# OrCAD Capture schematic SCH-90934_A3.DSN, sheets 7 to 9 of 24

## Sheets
7 C-20 REMOTE DEBUG: size A1
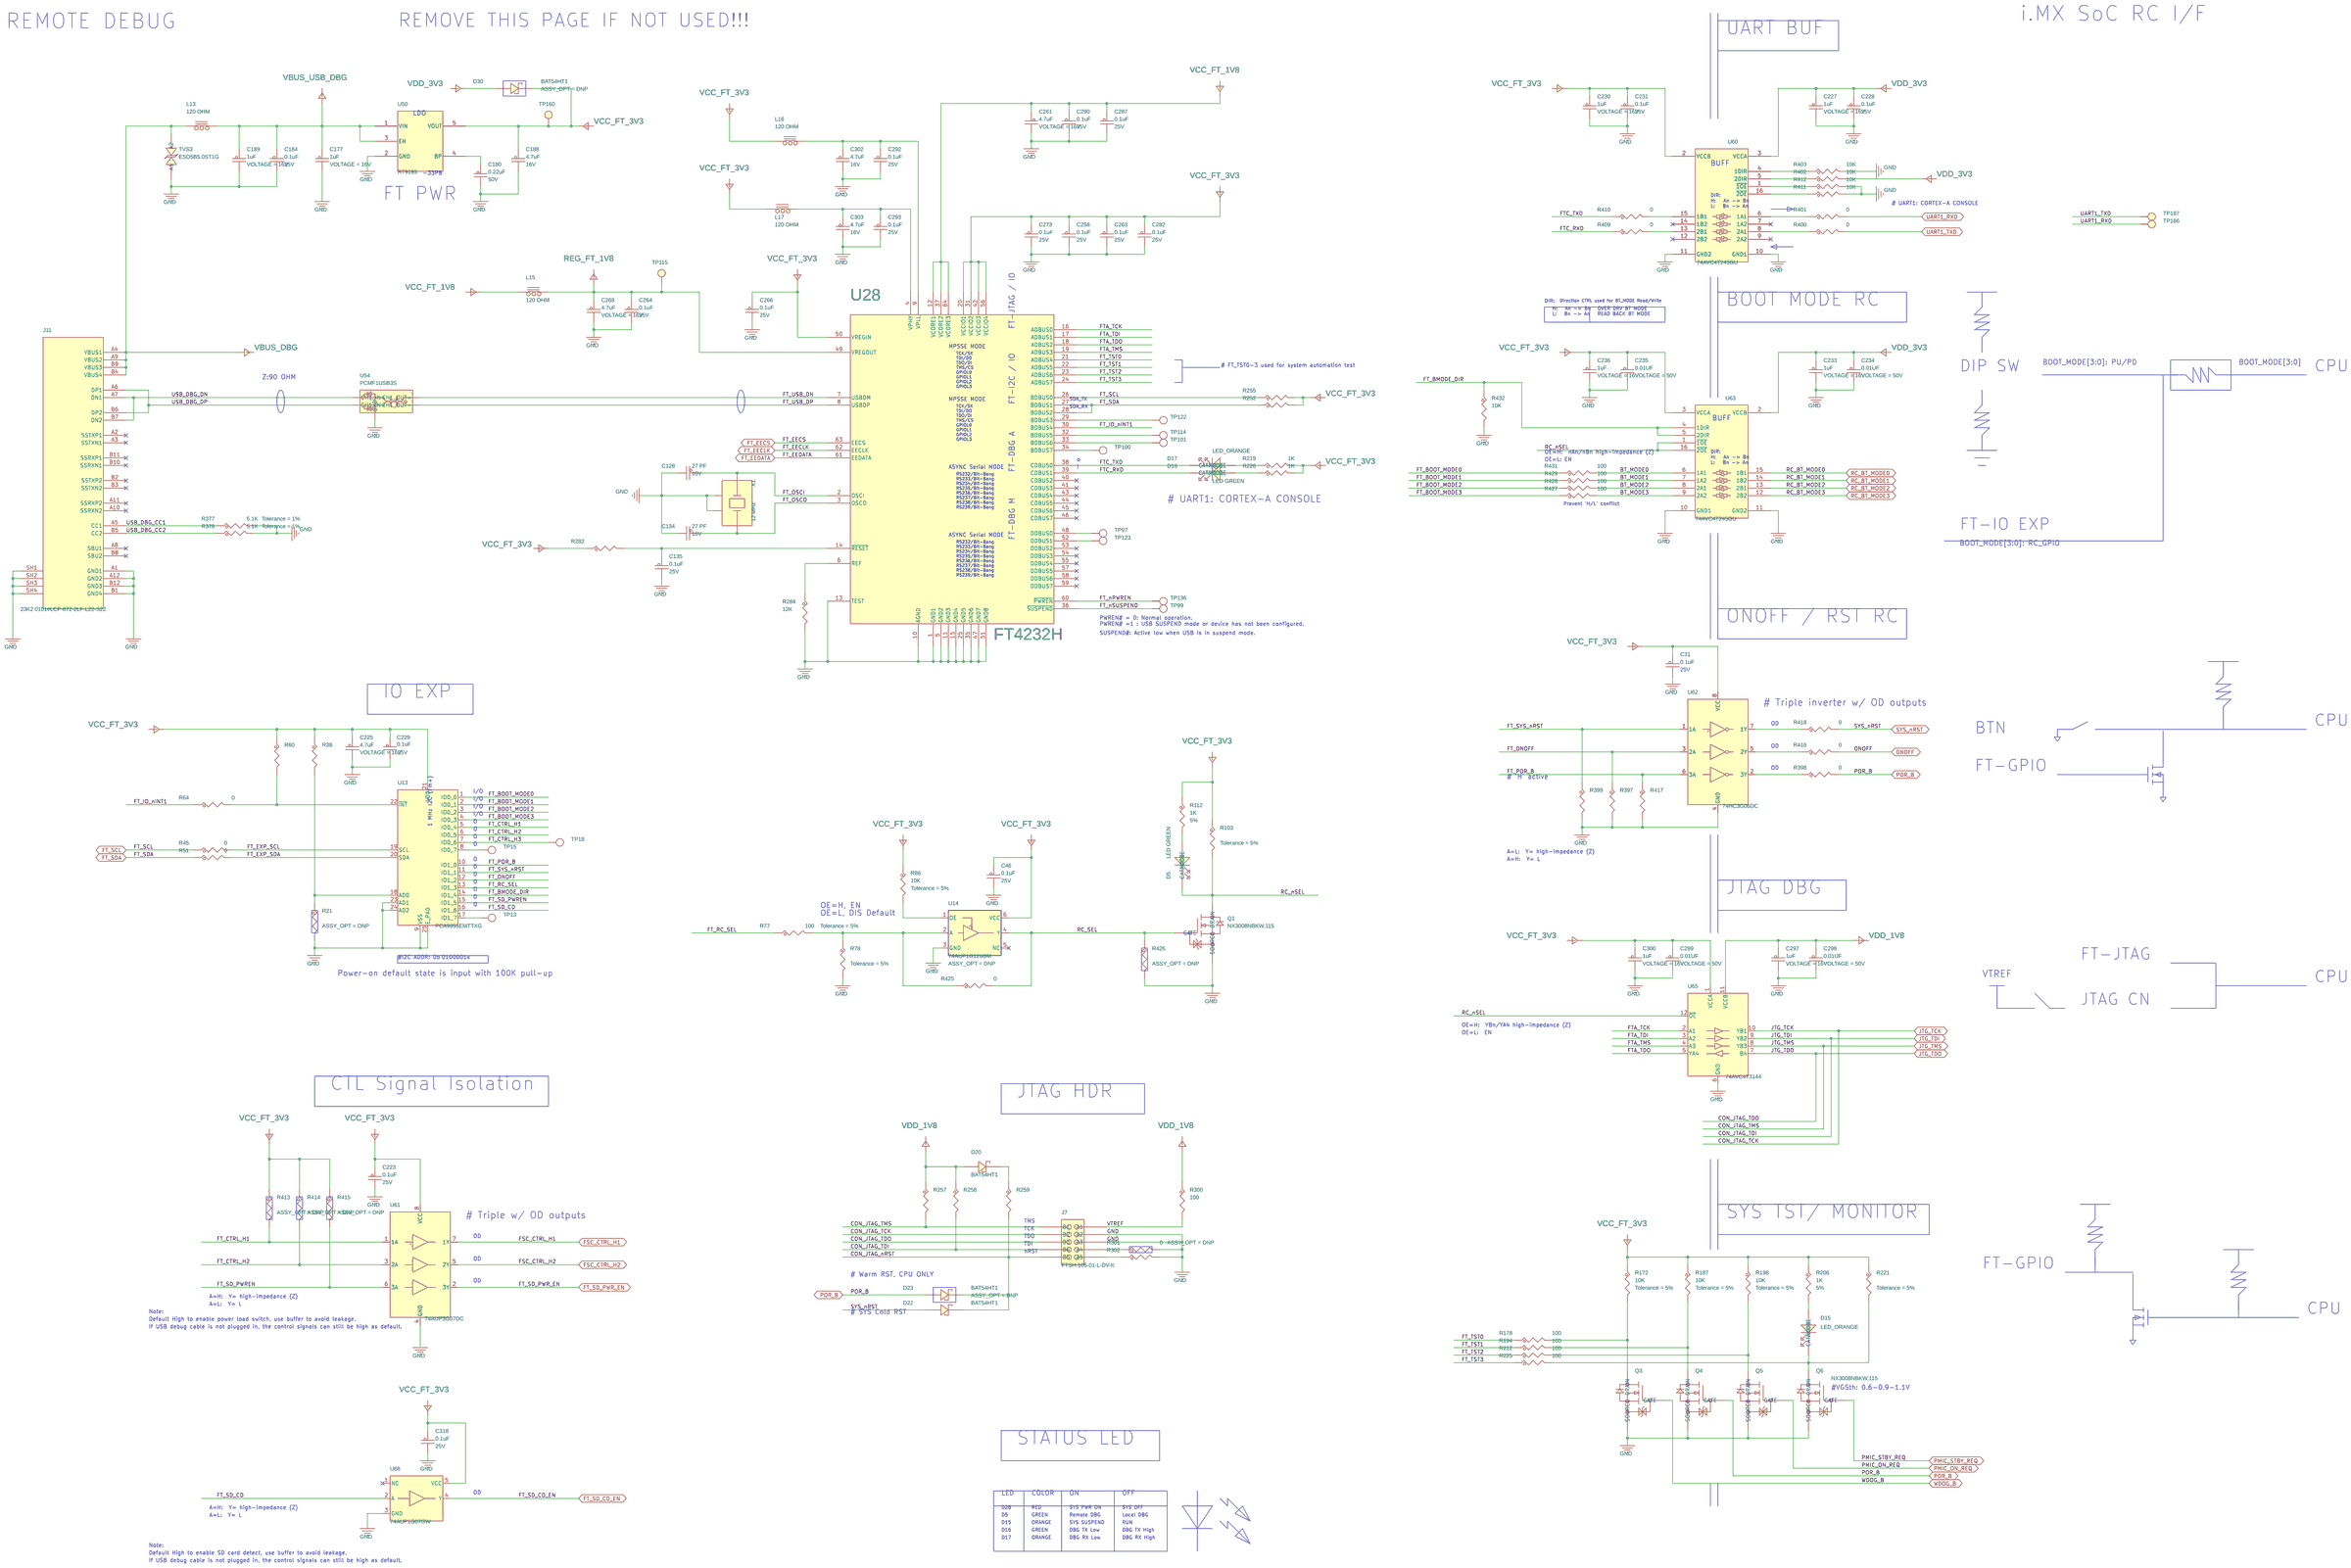
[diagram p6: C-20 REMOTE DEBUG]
8 C-19 PDM MIC: size A3
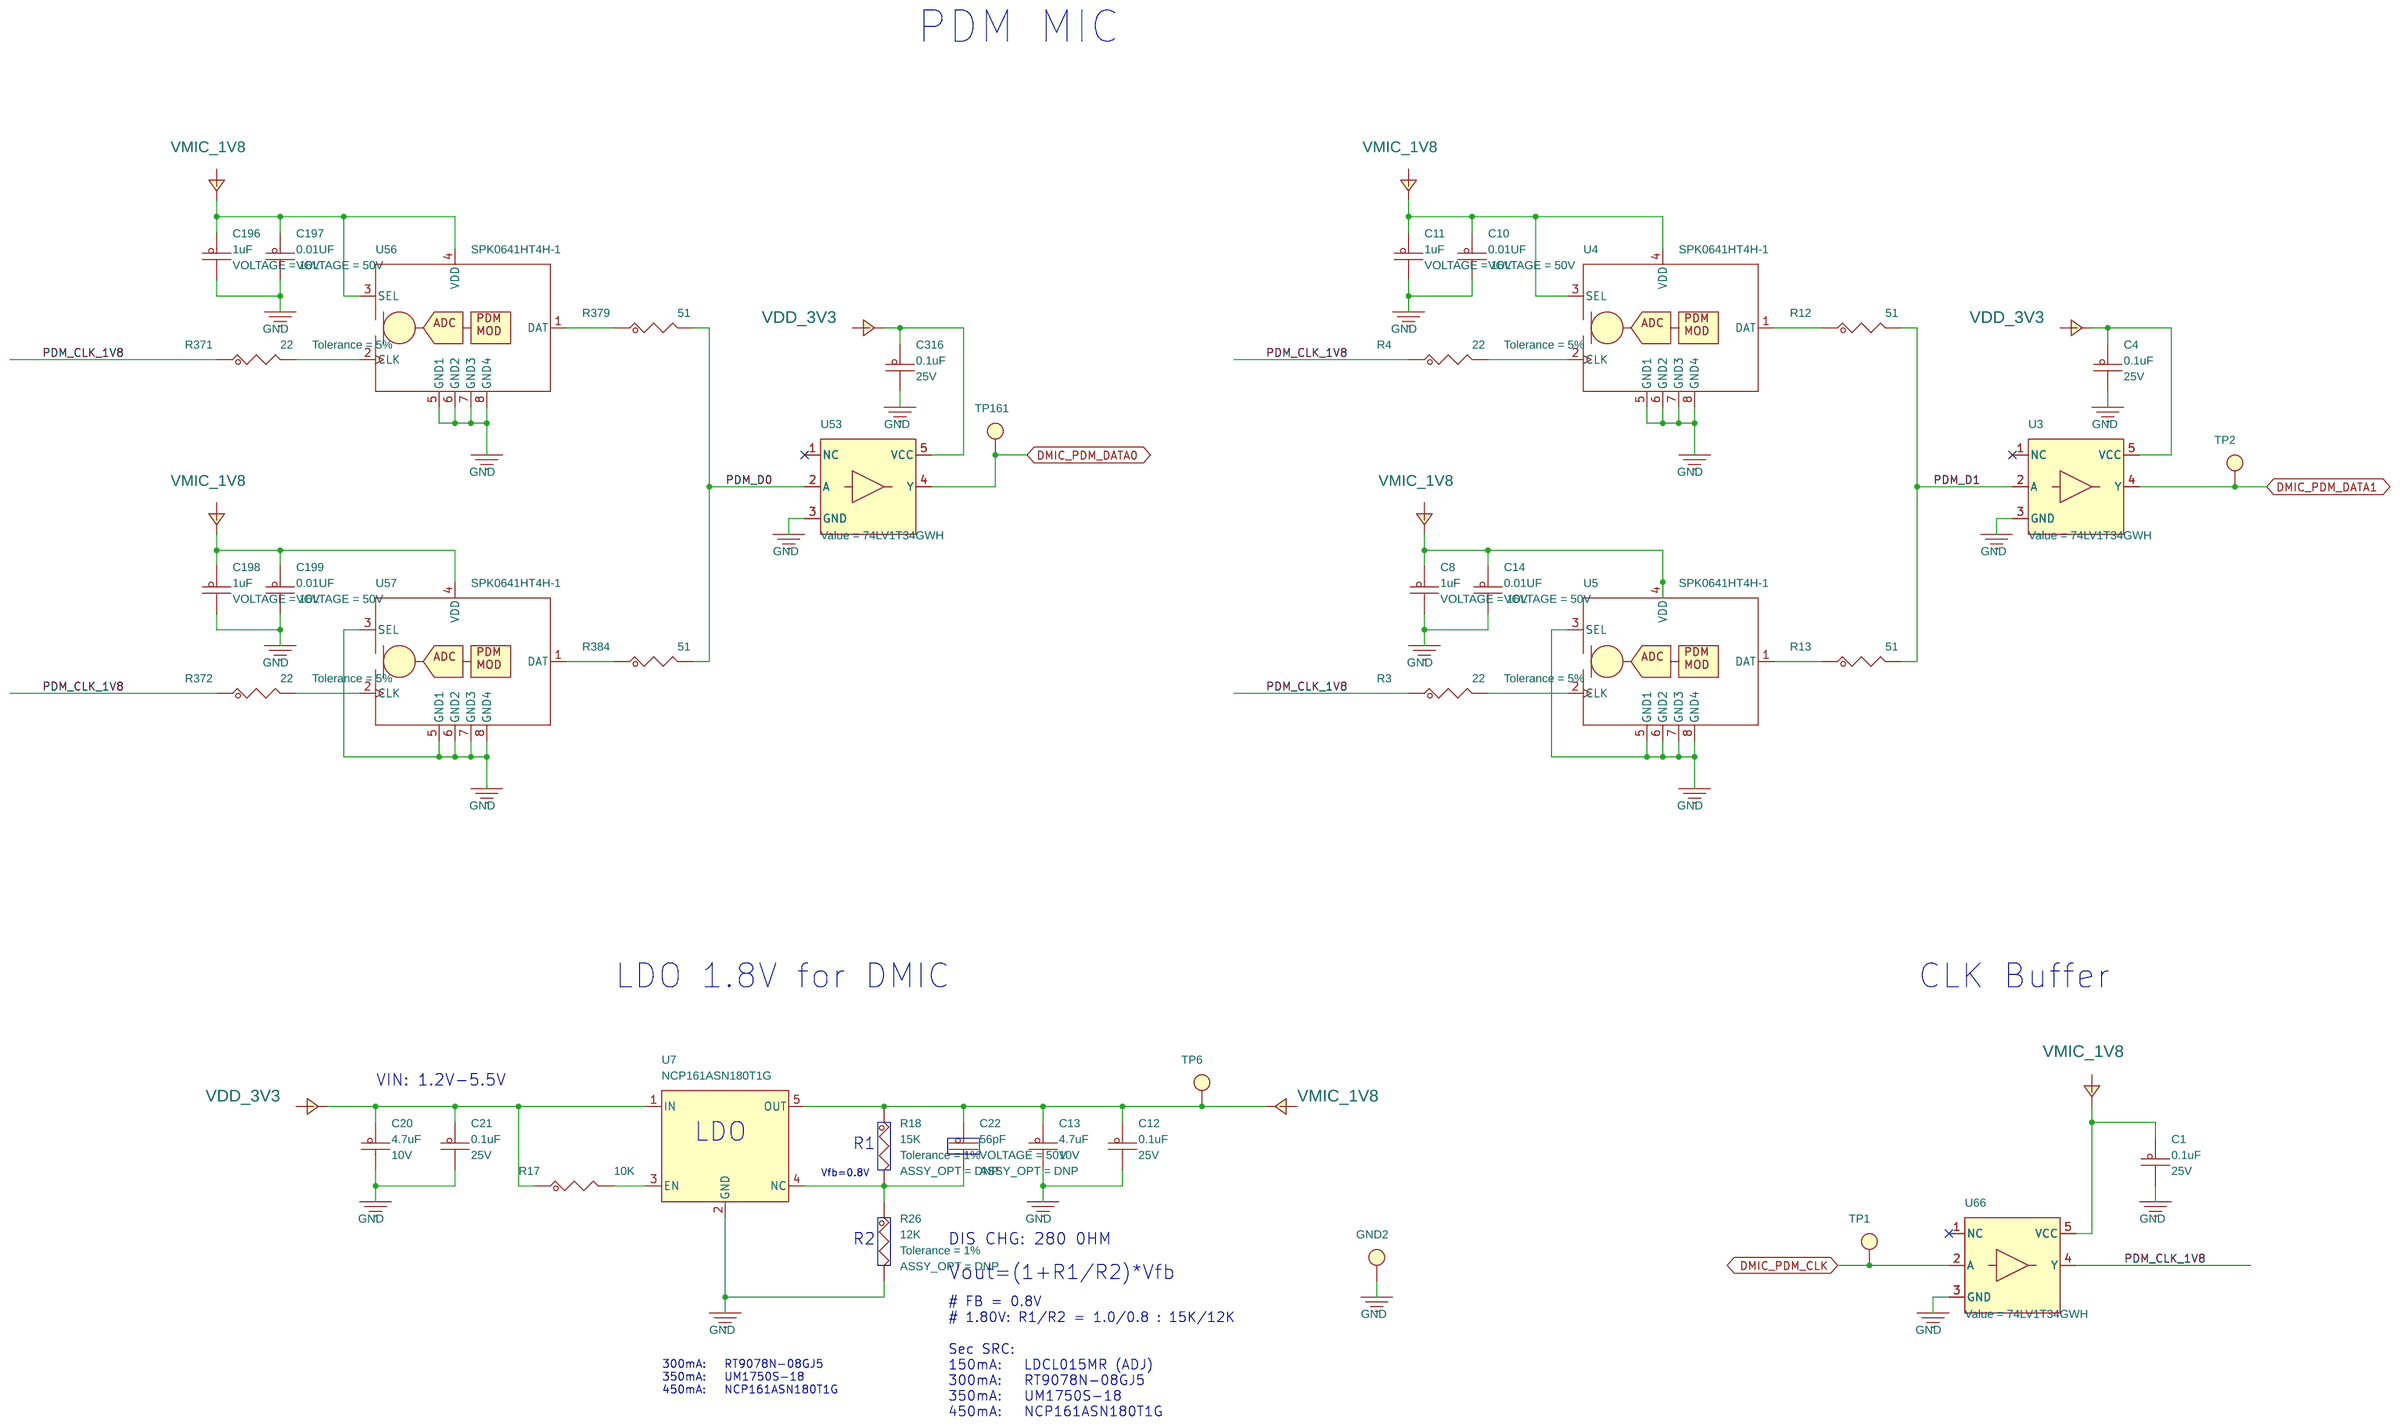
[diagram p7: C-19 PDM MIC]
9 C-18 AUDIO DAC: size A4
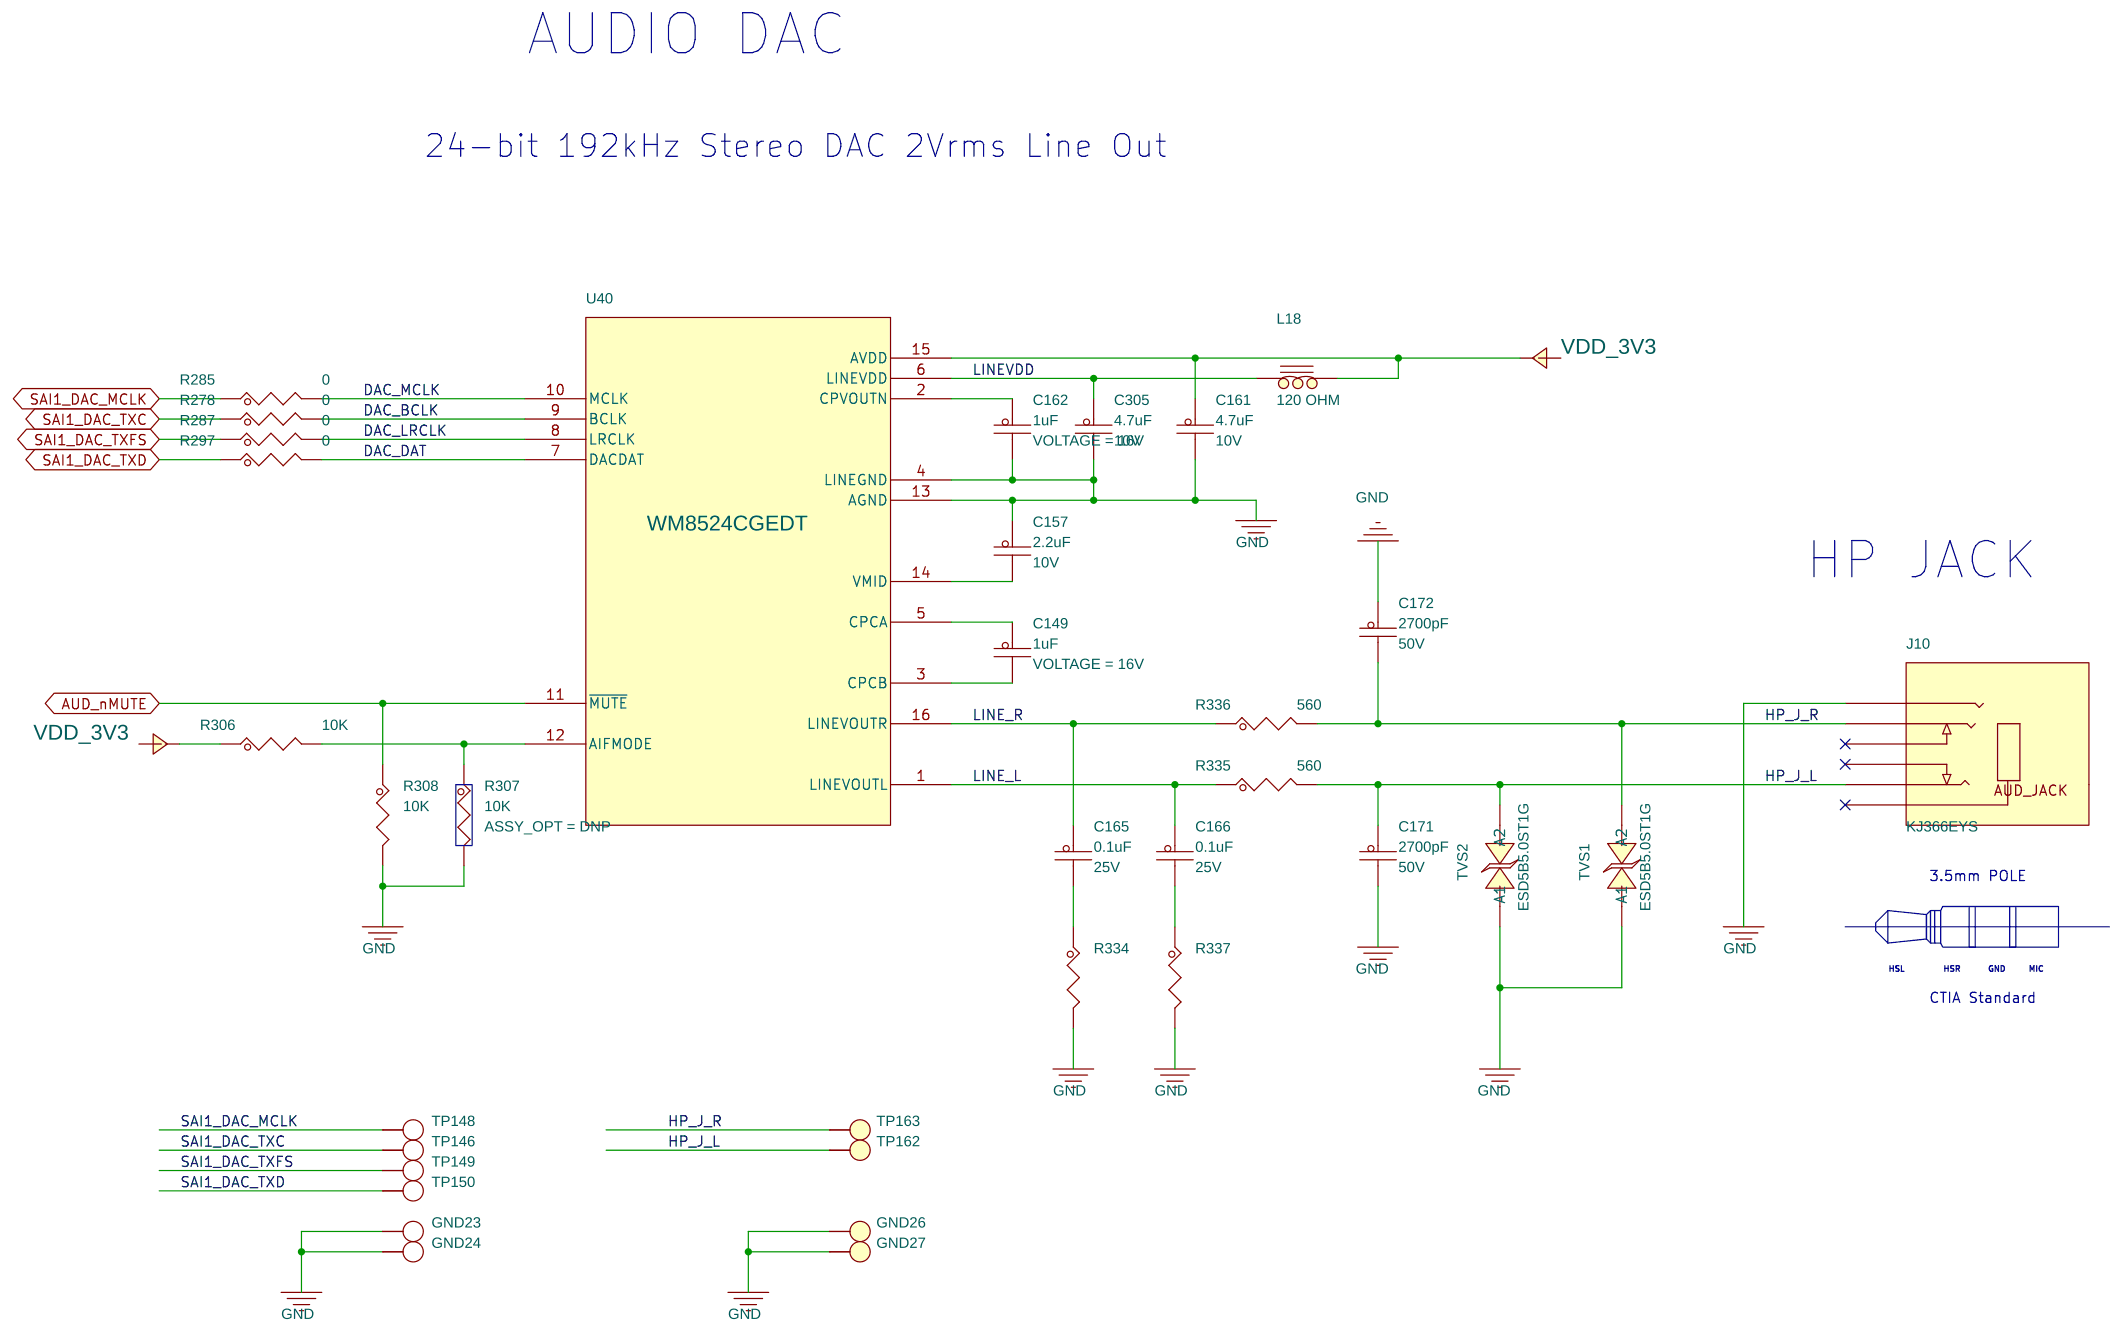
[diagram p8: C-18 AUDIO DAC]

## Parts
sheet C-18 AUDIO DAC
C149  1uF  [CC0402_25]
C157  2.2uF  [CC0402_25]
C161  4.7uF  [cc0402_tol0p15]
C162  1uF  [CC0402_25]
C165  0.1uF  [CC0402_25]
C166  0.1uF  [CC0402_25]
C171  2700pF  [0603_CC]
C172  2700pF  [0603_CC]
C305  4.7uF  [cc0402_tol0p15]
GND23  TPAD_020  [tpad_020]
GND24  TPAD_020  [tpad_020]
GND26  TP_35MIL  [testpoint_35mil]
GND27  TP_35MIL  [testpoint_35mil]
J10  KJ366EYS  [con6_audiojack_ra_th]
L18  120 OHM  [IND_0603]
R278  0  [0402_CC]
R285  0  [0402_CC]
R287  0  [0402_CC]
R297  0  [0402_CC]
R306  10K  [0402_CC]
R307  10K  [0402_CC]
R308  10K  [0402_CC]
R334  20  [0603_CC]
R335  560  [0603_CC]
R336  560  [0603_CC]
R337  20  [0603_CC]
TP146  TPAD_020  [tpad_020]
TP148  TPAD_020  [tpad_020]
TP149  TPAD_020  [tpad_020]
TP150  TPAD_020  [tpad_020]
TP162  TP_35MIL  [testpoint_35mil]
TP163  TP_35MIL  [testpoint_35mil]
TVS1  ESD5B5.0ST1G  [diode2_sod523]
TVS2  ESD5B5.0ST1G  [diode2_sod523]
U40  WM8524CGEDT  [tssop16]
sheet C-19 PDM MIC
C1  0.1uF  [CC0402_25]
C4  0.1uF  [CC0402_25]
C8  1uF  [CC0402_25]
C10  0.01UF  [CC0402_25]
C11  1uF  [CC0402_25]
C12  0.1uF  [CC0402_25]
C13  4.7uF  [cc0402_tol0p15]
C14  0.01UF  [CC0402_25]
C20  4.7uF  [cc0402_tol0p15]
C21  0.1uF  [CC0402_25]
C22  56pF  [CC0402_25]
C196  1uF  [CC0402_25]
C197  0.01UF  [CC0402_25]
C198  1uF  [CC0402_25]
C199  0.01UF  [CC0402_25]
C316  0.1uF  [CC0402_25]
GND2  TP_35MIL  [testpoint_35mil]
R3  22  [0402_CC]
R4  22  [0402_CC]
R12  51  [0402_CC]
R13  51  [0402_CC]
R17  10K  [0402_CC]
R18  15K  [RC0402_25]
R26  12K  [RC0402_25]
R371  22  [0402_CC]
R372  22  [0402_CC]
R379  51  [0402_CC]
R384  51  [0402_CC]
TP1  TP_35MIL  [testpoint_35mil]
TP2  TP_35MIL  [testpoint_35mil]
TP6  TP_35MIL  [testpoint_35mil]
TP161  TP_35MIL  [testpoint_35mil]
U3  74LV1T34GWH  [sc70-5]
U4  SPK0641HT4H-1  [lga8_3p1x4p1mm_spk0641]
U5  SPK0641HT4H-1  [lga8_3p1x4p1mm_spk0641]
U7  NCP161ASN180T1G  [SOT-23-5]
U53  74LV1T34GWH  [sc70-5]
U56  SPK0641HT4H-1  [lga8_3p1x4p1mm_spk0641]
U57  SPK0641HT4H-1  [lga8_3p1x4p1mm_spk0641]
U66  74LV1T34GWH  [sc70-5]
sheet C-20 REMOTE DEBUG
C31  0.1uF  [CC0402_25]
C46  0.1uF  [CC0402_25]
C128  27 PF  [CC0402_25]
C134  27 PF  [CC0402_25]
C135  0.1uF  [CC0402_25]
C177  1uF  [CC0402_25]
C180  0.22uF  [CC0402_25]
C184  0.1uF  [CC0402_25]
C188  4.7uF  [cc0402_tol0p15]
C189  1uF  [CC0402_25]
C223  0.1uF  [CC0402_25]
C225  4.7uF  [cc0402_tol0p15]
C227  1uF  [CC0402_25]
C228  0.1uF  [CC0402_25]
C229  0.1uF  [CC0402_25]
C230  1uF  [CC0402_25]
C231  0.1uF  [CC0402_25]
C233  1uF  [CC0402_25]
C234  0.01UF  [CC0402_25]
C235  0.01UF  [CC0402_25]
C236  1uF  [CC0402_25]
C258  0.1uF  [CC0402_25]
C261  4.7uF  [cc0402_tol0p15]
C263  0.1uF  [CC0402_25]
C264  0.1uF  [CC0402_25]
C266  0.1uF  [CC0402_25]
C268  4.7uF  [cc0402_tol0p15]
C273  0.1uF  [CC0402_25]
C282  0.1uF  [CC0402_25]
C287  0.1uF  [CC0402_25]
C290  0.1uF  [CC0402_25]
C292  0.1uF  [CC0402_25]
C293  0.1uF  [CC0402_25]
C297  1uF  [CC0402_25]
C298  0.01UF  [CC0402_25]
C299  0.01UF  [CC0402_25]
C300  1uF  [CC0402_25]
C302  4.7uF  [cc0402_tol0p15]
C303  4.7uF  [cc0402_tol0p15]
C318  0.1uF  [CC0402_25]
D5  LED GREEN  [LED_0603]
D15  LED_ORANGE  [led_0603_11mil]
D16  LED GREEN  [LED_0603]
D17  LED_ORANGE  [led_0603_11mil]
D20  BAT54HT1  [SOD323]
D22  BAT54HT1  [SOD323]
D23  BAT54HT1  [SOD323]
D30  BAT54HT1  [SOD323]
J7  FTSH-105-01-L-DV-K  [hdr205_10m_50_sm_k]
J11  23K2 0101#LCP-872-2LF-L22-S22  [con24_usb_typec_ra_smt_th_2p2l]
L13  120 OHM  [IND_0603]
L15  120 OHM  [IND_0603]
L16  120 OHM  [IND_0603]
L17  120 OHM  [IND_0603]
Q1  NX3008NBKW,115  [sc70_3]
Q3  NX3008NBKW,115  [sc70_3]
Q4  NX3008NBKW,115  [sc70_3]
Q5  NX3008NBKW,115  [sc70_3]
Q6  NX3008NBKW,115  [sc70_3]
R21  10K  [0402_CC]
R38  10K  [0402_CC]
R45  0  [0402_CC]
R51  0  [0402_CC]
R60  10K  [0402_CC]
R64  0  [0402_CC]
R77  100  [RC0402_25]
R78  10K  [0402_CC]
R86  10K  [0402_CC]
R103  10K  [0402_CC]
R112  1K  [0402_CC]
R172  10K  [0402_CC]
R178  100  [RC0402_25]
R187  10K  [0402_CC]
R194  100  [RC0402_25]
R198  10K  [0402_CC]
R206  1K  [0402_CC]
R212  100  [RC0402_25]
R219  1K  [0402_CC]
R221  10K  [0402_CC]
R225  100  [RC0402_25]
R226  1K  [0402_CC]
R252  2.2K  [0402_CC]
R255  2.2K  [0402_CC]
R257  10K  [0402_CC]
R258  10K  [0402_CC]
R259  10K  [0402_CC]
R282  10K  [0402_CC]
R284  12K  [0402_CC]
R300  100  [RC0402_25]
R301  0  [0402_CC]
R302  0  [0402_CC]
R377  5.1K  [RC0402_25]
R378  5.1K  [RC0402_25]
R397  10K  [0402_CC]
R398  0  [0402_CC]
R399  10K  [0402_CC]
R400  0  [0402_CC]
R401  0  [0402_CC]
R402  10K  [0402_CC]
R403  10K  [0402_CC]
R409  0  [0402_CC]
R410  0  [0402_CC]
R411  10K  [0402_CC]
R412  10K  [0402_CC]
R413  10K  [0402_CC]
R414  10K  [0402_CC]
R415  10K  [0402_CC]
R416  0  [0402_CC]
R417  10K  [0402_CC]
R418  0  [0402_CC]
R425  0  [0402_CC]
R426  10K  [0402_CC]
R427  100  [RC0402_25]
R428  100  [RC0402_25]
R429  100  [RC0402_25]
R431  100  [RC0402_25]
R432  10K  [0402_CC]
TP13  TPAD_020  [tpad_020]
TP15  TPAD_020  [tpad_020]
TP18  TPAD_020  [tpad_020]
TP97  TPAD_020  [tpad_020]
TP99  TPAD_020  [tpad_020]
TP100  TPAD_020  [tpad_020]
TP101  TPAD_020  [tpad_020]
TP114  TPAD_020  [tpad_020]
TP115  TP_35MIL  [testpoint_35mil]
TP122  TPAD_020  [tpad_020]
TP123  TPAD_020  [tpad_020]
TP136  TPAD_020  [tpad_020]
TP160  TP_35MIL  [testpoint_35mil]
TP186  TP_35MIL  [testpoint_35mil]
TP187  TP_35MIL  [testpoint_35mil]
TVS3  ESD5B5.0ST1G  [diode2_sod523]
U13  PCA9655EMTTXG  [qfn24_4X4_ep2p25mm]
U14  74AUP1G126GM  [udfn6_1x1p5mm]
U28  FT4232H  [lqfp64_0p5_10x10]
U50  RT9193  [sot23-5]
U54  PCMF1USB3S  [wlcsp5_0p4_0p82x1p22]
U60  74AVC4T245GU  [xqfn16_0p4_2p7x1p9]
U61  74AUP3G07DC  [ssop8_dcu]
U62  74HC3G06DC  [ssop8_dcu]
U63  74AVC4T245GU  [xqfn16_0p4_2p7x1p9]
U65  74AVC4T3144  [xqfn12_0p4_1p8x2p1]
U68  74AUP1G07GW  [sc70-5]
X1  12 MHz  [xtal_4_3p3x2p6mm]

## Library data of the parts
C149 C162 C189 = CAP_NP: CAP CER 1uF 16V 10% X5R 0402; AGILE_PN: 150-78973; CAD_APPROVED: Yes; FPLIST: CC0402_25,CC0402_HD,0402_CC,capc0402_l; HEIGHT: 0.55 MM; MFG_NAME01: TDK; MFG_PN01: C1005X5R1C105K; ROHS: Yes; Rated Voltage: 16V; Temp Range: -55C to +85C; Tolerance: 10%; VOLTAGE: 16V; voltage rating: 16V
C157 = CAP_NP: CAP CER 2.2uF 10V 10% X5R 0402; AGILE_PN: 150-78974; CAD_APPROVED: Yes; FPLIST: CC0402_25,CC0402_HD,0402_CC,capc0402_l; HEIGHT: 0.55 MM; MFG_NAME01: TDK; MFG_PN01: C1005X5R1A225K; Package Size: 0402; ROHS: Yes; Rated Voltage: 10V; Temp Range: -55C to +85C; Tolerance: 10%; VOLTAGE: 10V
C13 C20 C161 C305 = CAP_NP: CAP CER 4.7uF 10V 10% X5R 0402; AGILE_PN: 150-80044; CAD_APPROVED: Yes; FPLIST: cc0402_tol0p15,cc0402_tol0p15_ov,0402_cc_nsp; HEIGHT: 0.65MM; MFG_NAME01: SAMSUNG ELECTRO MECHANICS; MFG_PN01: CL05A475KP5NRNC; ROHS: Yes; Rated Voltage: 10V; Temp Range: -55C to +85C; Tolerance: 10%; VOLTAGE: 10V
C1 C4 C12 C21 C31 C46 C135 C165 C166 C184 C223 C228 C229 C231 C258 C263 C264 C266 C273 C282 C287 C290 C292 C293 C316 C318 = CAP_NP: CAP CER 0.1UF 25V 10% X5R 0402; AGILE_PN: 150-78633; CAD_APPROVED: Yes; FPLIST: CC0402_25,CC0402_HD,0402_CC,capc0402_l; HEIGHT: 0.55MM; MFG_NAME01: YAGEO AMERICA; MFG_PN01: CC0402KRX5R8BB104; Package Size: 0402; ROHS: Yes; Rated Voltage: 25V; Temp Range: -55C to +85C; Tolerance: 10%; VOLTAGE: 25V
C171 C172 = CAP_NP: CAP CER 2700pF 50V 5% C0G 0603; AGILE_PN: 150-78873; CAD_APPROVED: Yes; FPLIST: CC0603_OV,CC0603,0603_CC; HEIGHT: 0.87MM; MFG_NAME01: KEMET; MFG_PN01: C0603C272J5GACTU; Package Size: 0603; Package Type: Tape & reel; ROHS: Yes; Rated Voltage: 50V; Temp Range: -55C to +125C; Tolerance: 5%; VOLTAGE: 50V
GND23 GND24 TP13 TP15 TP18 TP97 TP99-TP101 TP114 TP122 TP123 TP136 TP146 TP148-TP150 = TESTLOOP: TEST POINT PAD 0.5MM DIA SMT, NO PART TO ORDER; AGILE_PN: 211-77484; ASSY_OPT: DNP; CAD_APPROVED: Yes; HEIGHT: 0.1MM; ROHS: Yes
GND2 GND26 GND27 TP1 TP2 TP6 TP115 TP160-TP163 TP186 TP187 = T_POINT_R: TEST POINT PAD .035 SMT, no part to order; AGILE_PN: 510-75618; ASSY_OPT: DNP; CAD_APPROVED: Yes; HEIGHT: 0.1MM; ROHS: Yes
J10 = CON_KJ366EYS_AUDIOJACK_6P: CON 6 AUDIO JACK 3.5MM SKT RA SMT -- 177H AU; AGILE_PN: 211-80200; CAD_APPROVED: Yes; HEIGHT: 4.5; MFG_NAME01: FODOT ELECTRONICS CO.,LTD.; MFG_PN01: KJ366EYS-00RJ03B; ROHS: Yes; Temp Range: -25 to +85°C; Temp_Range: -25 to +85°C
L13 L15-L18 = BEAD_0: IND FER BEAD 120OHM@100MHZ 2A 25% 0603; AGILE_PN: 180-78419; CAD_APPROVED: Yes; FPLIST: IND_0603,0603_CC; HEIGHT: 0.95; MFG_NAME01: MURATA; MFG_PN01: BLM18PG121SN1D; ROHS: Yes
R64 R278 R285 R287 R297 R398 R400 R401 R409 R410 R416 R418 R425 = RES: RES MF ZERO OHM 1/16W 5% 0402; AGILE_PN: 470-75394; CAD_APPROVED: Yes; FPLIST: RC0402_25,RC0402_HD,RC0402_X2,0402_CC; HEIGHT: 0.45; MFG_NAME01: YAGEO AMERICA; MFG_PN01: RC0402JR-070RL; ROHS: Yes; Temp Range: -55 to +155C; Tolerance: 5%; VOLTAGE: 1/16W
R17 R38 R60 R78 R86 R103 R172 R187 R198 R221 R257-R259 R282 R306 R308 R397 R399 R402 R403 R411 R412 R417 R432 = RES: RES MF 10K 1/16W 5% 0402; AGILE_PN: 470-75557; CAD_APPROVED: Yes; FPLIST: RC0402_25,RC0402_HD,0402_CC; HEIGHT: 0.4 MM; MFG_NAME01: VISHAY INTERTECHNOLOGY; MFG_PN01: CRCW040210K0JNED; ROHS: Yes; Tolerance: 5%
R21 R307 R413-R415 R426 = RES: RES MF 10K 1/16W 5% 0402; AGILE_PN: 470-75557; ASSY_OPT: DNP; CAD_APPROVED: Yes; FPLIST: RC0402_25,RC0402_HD,0402_CC; HEIGHT: 0.4 MM; MFG_NAME01: VISHAY INTERTECHNOLOGY; MFG_PN01: CRCW040210K0JNED; ROHS: Yes; Tolerance: 5%
R334 R337 = RES: RES MF 20.0OHM 1/10W 1% 0603; AGILE_PN: 470-75405; CAD_APPROVED: Yes; FPLIST: RC0603_OV,RC0603,0603_CC; HEIGHT: 0.55 MM; MFG_NAME01: KOA SPEER; MFG_PN01: RK73H1JTTD20R0F; ROHS: Yes; SIGNAL_MODEL: DEFAULT_RESISTOR_20OHM_2_1; Tolerance: 1%
R335 R336 = RES: RES TF 560 OHM 1/10W 5% 200PPM/C 0603; AGILE_PN: 470-81150; CAD_APPROVED: Yes; FPLIST: RC0603_OV,RC0603,0603_CC; HEIGHT: 0.55MM; MFG_NAME01: BOURNS; MFG_PN01: CR0603-JW-561ELF; ROHS: Yes; Tolerance: 5%
TVS1-TVS3 = DIODE_TVS_BIDIR: DIODE SUPPRESSOR 16A@30NS 5V@1UA SOD-523; 3D_Mechanical_Footprint_File: http://fcl.am.freescale.net/ALLEGRO/step/diode2_sod523.STEP; AGILE_PN: 480-76937; CAD_APPROVED: Yes; HEIGHT: 0.7; MFG_NAME01: ON SEMICONDUCTOR; ROHS: Yes
U40 = WM8524GEDT: IC DAC STEREO 24BIT 192kHz 2.97-3.63V TSSOP16; 3D_Mechanical_Footprint_File: http://fcl.am.freescale.net/ALLEGRO/step/tssop16.step; AGILE_PN: 315-81421; CAD_APPROVED: Yes; HEIGHT: 1.2; MFG_NAME01: CIRRUS LOGIC; ROHS: Yes; Temp Range: -40C to +85C; Temp_Range: -40C to +85C; VOLTAGE: 2.97-3.63V
C8 C11 C196 C198 = CAP_NP: CAP CER 1uF 16V 10% X5R 0402; AGILE_PN: 150-78973; CAD_APPROVED: Yes; FPLIST: CC0402_25,CC0402_HD,0402_CC,capc0402_l; HEIGHT: 0.55 MM; MFG_NAME01: TDK; MFG_PN01: C1005X5R1C105K; ROHS: Yes; Rated Voltage: 16V; SIGNAL_MODEL: DEFAULT_CAPACITOR_1e+06pF_2_1; Temp Range: -55C to +85C; Temp_Range: -55°C to +85°C; Tolerance: 10%; VOLTAGE: 16V; voltage rating: 16V
C10 C14 C197 C199 = CAP_NP: CAP CER 0.01UF 50V 10% X7R 0402; AGILE_PN: 150-30114; CAD_APPROVED: Yes; FPLIST: CC0402_25,CC0402_HD,0402_CC; HEIGHT: 0.55 MM; MFG_NAME01: MURATA; MFG_PN01: GRM155R71H103KA88D; ROHS: Yes; Rated Voltage: 50V; TOL: 10%; Temp Range: -55C to +125C; Tolerance: 10%; VOLTAGE: 50V
C22 = CAP_NP: CAP CER 56PF 50V 5% C0G 0402; AGILE_PN: 150-80332; ASSY_OPT: DNP; CAD_APPROVED: Yes; FPLIST: CC0402_25,CC0402_HD,0402_CC,capc0402_l; HEIGHT: 0.55MM; MFG_NAME01: KEMET; MFG_PN01: C0402C560J5GAC; Package Size: 0402; ROHS: Yes; Rated Voltage: 50V; Temp Range: -55C to +125C; Tolerance: 5%; VOLTAGE: 50V
R3 R4 R371 R372 = RES: RES MF 22 OHM 1/16W 5% 0402; AGILE_PN: 470-75605; CAD_APPROVED: Yes; FPLIST: RC0402_25,RC0402_HD,0402_CC; HEIGHT: 0.4MM; MFG_NAME01: BOURNS; MFG_PN01: CR0402-JW-220GLF; ROHS: Yes; Tolerance: 5%
R12 R13 R379 R384 = RES: RES MF 51 OHM 1/16W 5% 0402; AGILE_PN: 470-76089; CAD_APPROVED: Yes; FPLIST: RC0402_25,RC0402_HD,0402_CC; HEIGHT: 0.40 MM; MFG_NAME01: YAGEO AMERICA; MFG_PN01: RC0402JR-0751RL; ROHS: Yes; Tolerance: 5%
R18 = RES: RES MF 15K  1/16W 1% 0402; AGILE_PN: 470-30965; ASSY_OPT: DNP; CAD_APPROVED: Yes; FPLIST: RC0402_25,RC0402_HD,0402_CC; HEIGHT: 0.40 MM; MFG_NAME01: WALSIN TECHNOLOGY CORP.; MFG_PN01: WR04X1502FTL; ROHS: Yes; Tolerance: 1%
R26 = RES: RES MF 12K 1/10W 1% AEC-Q200 0402; AGILE_PN: 470-30955; ASSY_OPT: DNP; CAD_APPROVED: Yes; FPLIST: RC0402_25,RC0402_HD,0402_CC; HEIGHT: 0.40 MM; MFG_NAME01: KOA SPEER; MFG_PN01: RK73H1ETTP1202F; ROHS: Yes; Temp Range: -55C to +155C; Tolerance: 1%; VOLTAGE: 50V
U3 U53 U66 = 74LV1T34GWH_TSSOP6: IC BUF NON-INVERT 1.6-5.5V TSSOP5; 3D_Mechanical_Footprint_File: http://fcl.am.freescale.net/ALLEGRO/step/sc70-5.STEP; AGILE_PN: 312-83344; CAD_APPROVED: Yes; HEIGHT: 1.1; MFG_NAME01: Nexperia; Package Size: TSSOP-5; ROHS: Yes; Temp Range: -40  °C - 125 °C
U4 U5 U56 U57 = SPK0641HT4H_8P_A: IC MIC MEMS PDM DIGITAL SISONIC -26DB 1.6-3.6V LGA8; 3D_Mechanical_Footprint_File: http://fcl.am.freescale.net/ALLEGRO/step/lga8_3p1x4p1mm_spk0641.STEP; AGILE_PN: 510-78247; CAD_APPROVED: Yes; HEIGHT: 1.1; MFG_NAME01: KNOWLES ACOUSTICS; ROHS: Yes
U7 = NCP161ASN180T1G_A: IC VREG LDO FIXED 1.8V 450mA 1.9-5.5V SOT23-5; 3D_Mechanical_Footprint_File: http://fcl.am.freescale.net/ALLEGRO/step/sot-23-5.STEP; AGILE_PN: 315-83463; CAD_APPROVED: Yes; HEIGHT: 1.3; MFG_NAME01: ON SEMICONDUCTOR; ROHS: Yes; Temp Range: -40°C ~ 125°C (TJ); VOLTAGE: 1.9-5.5V
C128 C134 = CAP_NP: CAP CER 27PF 16V 5% C0G 0402; AGILE_PN: 150-75267; CAD_APPROVED: Yes; EN: 102-1-02308; FPLIST: CC0402_25,CC0402_HD,0402_CC; HEIGHT: 0.56 MM; MFG_NAME01: AVX; MFG_PN01: 0402YA270JAT2A; PRIORITY_PN: 021-00234; Package Size: 0402; Package Type: Tape & reel; ROHS: Yes; ROOM: RGMII_PHY; Rated Voltage: 16V; SIGNAL_MODEL: DEFAULT_CAPACITOR_22pF_2_1; TOL: 5%; Temp Range: -55C to +125C; Tolerance: 5%; VOLTAGE: 16V; WVDC: 50V
C177 C227 C230 C233 C236 C297 C300 = CAP_NP: CAP CER 1uF 16V 10% X5R 0402; AGILE_PN: 150-78973; CAD_APPROVED: Yes; FPLIST: CC0402_25,CC0402_HD,0402_CC,capc0402_l; HEIGHT: 0.55 MM; MFG_NAME01: TDK; MFG_PN01: C1005X5R1C105K; ROHS: Yes; Rated Voltage: 16V; SIGNAL_MODEL: DEFAULT_CAPACITOR_1e+06pF_2_1; TOL: 10%; Temp Range: -55C to +85C; Tolerance: 10%; VOLTAGE: 16V; voltage rating: 16V
C180 = CAP_NP: CAP CER 0.22uF 50V 10% X5R 0402; AGILE_PN: 150-79999; CAD_APPROVED: Yes; FPLIST: CC0402_25,CC0402_HD,0402_CC; HEIGHT: 0.55MM; MFG_NAME01: TAIYO YUDEN; MFG_PN01: UMK105BJ224KV-F; Package Size: 0402; ROHS: Yes; Rated Voltage: 50V; Temp Range: -55C to +85C; Temp_Range: -55°C to +85°C; Tolerance: 10%; VOLTAGE: 50V
C188 C302 C303 = CAP_NP: CAP CER 4.7uF 10V 10% X5R 0402; AGILE_PN: 150-80044; CAD_APPROVED: Yes; FPLIST: CC0603_OV,CC0603,cc0603_0805_nsp,0603_CC_NSP; HEIGHT: 0.65MM; MFG_NAME01: SAMSUNG ELECTRO MECHANICS; MFG_PN01: CL05A475KP5NRNC; ROHS: Yes; Rated Voltage: 10V; Temp Range: -55C to +85C; Tolerance: 10%; VOLTAGE: 16V
C225 C261 C268 = CAP_NP: CAP CER 4.7uF 10V 10% X5R 0402; AGILE_PN: 150-80044; CAD_APPROVED: Yes; FPLIST: CC0603_OV,CC0603,cc0603_0805_nsp,0603_CC_NSP; HEIGHT: 0.65MM; MFG_NAME01: SAMSUNG ELECTRO MECHANICS; MFG_PN01: CL05A475KP5NRNC; ROHS: Yes; Rated Voltage: 10V; Temp Range: -55C to +85C; Tolerance: 10%; VOLTAGE: 16V; voltage rating: 6.3V
C234 C235 C298 C299 = CAP_NP: CAP CER 0.01UF 50V 10% X7R 0402; AGILE_PN: 150-30114; CAD_APPROVED: Yes; FPLIST: CC0402_25,CC0402_HD,0402_CC; HEIGHT: 0.55 MM; MFG_NAME01: MURATA; MFG_PN01: GRM155R71H103KA88D; ROHS: Yes; Rated Voltage: 50V; Temp Range: -55C to +125C; Tolerance: 10%; VOLTAGE: 50V
D5 D16 = LED: LED GRN SGL 25MA SMT 0603; AGILE_PN: 370-76672; CAD_APPROVED: Yes; HEIGHT: 0.8; MFG_NAME01: DIALIGHT; MFG_PN01: 598-8070-107F; ROHS: Yes; Rated Voltage: 2V; VOLTAGE: 2V
D15 D17 = LED: LED OR SGL 20MA 0603; 3D_Mechanical_Footprint_File: http://fcl.am.freescale.net/ALLEGRO/step/led_0603_11mil.STEP; AGILE_PN: 370-76572; CAD_APPROVED: Yes; HEIGHT: 0.28; MFG_NAME01: KINGBRIGHT; MFG_PN01: APG1608SEKC/T; ROHS: Yes; Rated Voltage: 2V; Temp Range: -40°C to +85°C; Temp_Range: -40°C to +85°C; VOLTAGE: 2v
D20 D22 = DIODE_SCHTKY: DIODE SCH 30V 200MA -- SOD323; AGILE_PN: 480-30039; CAD_APPROVED: Yes; HEIGHT: 1.15; MFG_NAME01: ON SEMICONDUCTOR; MFG_PN01: BAT54HT1G
D23 D30 = DIODE_SCHTKY: DIODE SCH 30V 200MA -- SOD323; AGILE_PN: 480-30039; ASSY_OPT: DNP; CAD_APPROVED: Yes; HEIGHT: 1.15; MFG_NAME01: ON SEMICONDUCTOR; MFG_PN01: BAT54HT1G
J7 = CONN_HDR_5X2: HDR 2X5 SMT 50MIL CTR 246H AU; 3D_Mechanical_Footprint_File: http://fcl.am.freescale.net/ALLEGRO/step/hdr205_10m_50_sm_k.STEP; AGILE_PN: 211-79478; CAD_APPROVED: Yes; HEIGHT: 6.25; MFG_NAME01: SAMTEC; ROHS: Yes
J11 = USB24_TYPEC_SH4: CON 24 USB TYPE C RA SHLD HYBRID SMT-TH 0.5MM SP 145H AU 87L; AGILE_PN: 211-83409; CAD_APPROVED: Yes; HEIGHT: 3.67; MFG_NAME01: ANYTRONIC CORPORATION LIMITED; MFG_PN01: 23K20101#LCP-872-2LF-L22-S22; ROHS: Yes; Temp Range: -55°C to +105°C
Q1 Q3-Q6 = NX3008NBKW_SOT323: TRAN NMOS SW 30V 350mA AEC-Q101 SC-70; 3D_Mechanical_Footprint_File: http://fcl.am.freescale.net/ALLEGRO/step/sc70_3.STEP; AGILE_PN: 480-79736; CAD_APPROVED: Yes; HEIGHT: 1.1; MFG_NAME01: NEXPERIA; ROHS: Yes
R45 R51 = RES: RES MF ZERO OHM 1/16W 5% 0402; AGILE_PN: 470-75394; CAD_APPROVED: Yes; FPLIST: RC0402_25,RC0402_HD,RC0402_X2,0402_CC; HEIGHT: 0.45; MFG_NAME01: YAGEO AMERICA; MFG_PN01: RC0402JR-070RL; ROHS: Yes; Temp Range: -55 to +155C; Temp_Range: -55°C to +155°C; Tolerance: 5%; VOLTAGE: 1/16W
R77 R178 R194 R212 R225 R300 R427-R429 R431 = RES: RES MF 100 OHM 1/16W 5% 0402; AGILE_PN: 470-82142; CAD_APPROVED: Yes; FPLIST: RC0402_25,RC0402_HD,RC0402_X2,0402_CC; HEIGHT: 0.45MM; MFG_NAME01: SMEC; MFG_PN01: RC73L2Z101JTF; ROHS: Yes; Temp Range: -55°C to +175°C; Tolerance: 5%
R112 R206 R219 R226 = RES: RES MF 1.0K 1/16W 5% 0402; AGILE_PN: 470-75555; CAD_APPROVED: Yes; FPLIST: RC0402_25,RC0402_HD,RC0402_X2,0402_CC,CAPC0402_L; HEIGHT: 0.41mm; MFG_NAME01: VISHAY INTERTECHNOLOGY; MFG_PN01: CRCW04021K00JNED; ROHS: Yes; Tolerance: 5%
R252 R255 = RES: RES MF 2.2K 1/16W 5% 0402; AGILE_PN: 470-76602; CAD_APPROVED: Yes; FPLIST: RC0402_25,RC0402_HD,0402_CC; HEIGHT: 0.4 MM; MFG_NAME01: YAGEO AMERICA; MFG_PN01: RC0402JR-072K2L; RATING: 1/16W; ROHS: Yes; Tolerance: 5%
R284 = RES: RES MF 12K 1/10W 1% AEC-Q200 0402; AGILE_PN: 470-30955; CAD_APPROVED: Yes; EN: 101-1-03373; FPLIST: RC0402_25,RC0402_HD,0402_CC; HEIGHT: 0.40 MM; MFG_NAME01: KOA SPEER; MFG_PN01: RK73H1ETTP1202F; ROHS: Yes; TOL: 1%; Temp Range: -55C to +155C; Tolerance: 1%; VOLTAGE: 50V
R301 = RES: RES MF ZERO OHM 1/16W 5% 0402; AGILE_PN: 470-75394; ASSY_OPT: DNP; CAD_APPROVED: Yes; FPLIST: RC0402_25,RC0402_HD,RC0402_X2,0402_CC; HEIGHT: 0.45; MFG_NAME01: YAGEO AMERICA; MFG_PN01: RC0402JR-070RL; ROHS: Yes; Temp Range: -55 to +155C; Tolerance: 5%; VOLTAGE: 1/16W
R302 = RES: RES MF ZERO OHM 1/16W 5% 0402; AGILE_PN: 470-75394; CAD_APPROVED: Yes; FPLIST: RC0402_25,RC0402_HD,RC0402_X2,0402_CC; HEIGHT: 0.45; MFG_NAME01: YAGEO AMERICA; MFG_PN01: RC0402JR-070RL; ROHS: Yes; SIGNAL_MODEL: DEFAULT_RESISTOR_10000OHM_2_1; TOL: 1%; Temp Range: -55 to +155C; Tolerance: 5%; VOLTAGE: 1/16W
R377 R378 = RES: RES MF 5.1K  1/16W 1% 0402; AGILE_PN: 470-30914; CAD_APPROVED: Yes; FPLIST: RC0402_25,RC0402_HD,0402_CC; HEIGHT: 0.40 MM; MFG_NAME01: YAGEO AMERICA; MFG_PN01: RC0402FR-075K1L; ROHS: Yes; Tolerance: 1%
U13 = PCA9655EMTTXG_WQFN24_A: IC I/O EXPANDER 16BIT I2C 1.65-5.5V WQFN24; 3D_Mechanical_Footprint_File: http://fcl.am.freescale.net/ALLEGRO/step/qfn24_4X4_ep2p25mm.STEP; AGILE_PN: 312-83382; CAD_APPROVED: Yes; HEIGHT: 0.8; MFG_NAME01: onsemi; Package Size: 24-WFQFN Exposed Pad; ROHS: Yes; Supply Voltage: 1.65V ~ 5.5V; Temp Range: -55 to +125°C
U14 = 74AUP1G126GM: IC BUFFER/LINE DRIVER 3STATE 0.8-3.6V XSON6; AGILE_PN: 312-82356; ASSY_OPT: DNP; CAD_APPROVED: Yes; HEIGHT: 0.5; MFG_NAME01: Nexperia; MFG_PN01: 74AUP1G126GM,115; Package Size: XSON-6; ROHS: Yes; Supply Voltage: 1.8 V, 2.5 V, 3.3 V
U28 = FT4232HL_LQFP64: IC QUAD USB UART/FIFO 3.3V LQFP64; 3D_Mechanical_Footprint_File: http://fcl.am.freescale.net/ALLEGRO/step/lqfp64_0p5_10x10.step; AGILE_PN: 312-81268; CAD_APPROVED: Yes; EN: 301-0-02252; HEIGHT: 1.6; MFG_NAME01: FUTURE TECHNOLOGY DEVICES INTERNATIONAL LTD.; MFG_PN01: FT4232HL-REEL; ROHS: Yes; VOLTAGE: 3-3.6V
U50 = RT9193-33PB: IC VREG LDO 3.3V 300MA SOT-23-5; AGILE_PN: 315-76265; CAD_APPROVED: Yes; HEIGHT: 1.295; MFG_NAME01: RICHTEK; ROHS: Yes
U54 = PESD1USB30_5P: IC EMI FILTER ESD PROTECTION 15kV/LINE WLCSP5; 3D_Mechanical_Footprint_File: http://fcl.am.freescale.net/ALLEGRO/step/wlcsp5_0p4_0p82x1p22.STEP; AGILE_PN: 315-84061; CAD_APPROVED: Yes; HEIGHT: 0.6; MFG_NAME01: NEXPERIA; MFG_PN01: PCMF1USB3SZ; ROHS: Yes
U60 U63 = 74AVC4T245GU_XQFN16: IC XCVR VXLTR 4BIT DUAL 0.8-3.6V XQFN16; 3D_Mechanical_Footprint_File: http://fcl.am.freescale.net/ALLEGRO/step/xqfn16_0p4_2p7x1p9.STEP; AGILE_PN: 312-82314; CAD_APPROVED: Yes; HEIGHT: 0.5; MFG_NAME01: Nexperia; ROHS: Yes; Temp Range: -40°C ~ 125°C
U61 = SN74AUP3G04_A: IC TRIPLE BUF WITH OPEN DRAIN OUTPUT 0.8-3.6V VSSOP8; 3D_Mechanical_Footprint_File: http://fcl.am.freescale.net/ALLEGRO/step/ssop8_dcu.STEP; AGILE_PN: 312-83486; CAD_APPROVED: Yes; HEIGHT: 1; MFG_NAME01: NEXPERIA; ROHS: Yes; Temp Range: -40  °C to +125 °C
U62 = 74HC3G06DC: IC INV 3CH W/OPEN DRAIN OUT 2.0-6.0V VSSOP8; 3D_Mechanical_Footprint_File: http://fcl.am.freescale.net/ALLEGRO/step/ssop8_dcu.STEP; AGILE_PN: 312-83300; CAD_APPROVED: Yes; HEIGHT: 1.0; MFG_NAME01: NEXPERIA; ROHS: Yes; Temp Range: -40C to +125C; VOLTAGE: 2.0-6.0V
U65 = 74AVC4T3144_12P_A: IC BUF DUAL 4BIT NON-INVERT TS 0.8-3.6V XQFN12; 3D_Mechanical_Footprint_File: http://fcl.am.freescale.net/ALLEGRO/step/xqfn12_0p4_1p8x2p1.step; AGILE_PN: 315-82443; CAD_APPROVED: Yes; HEIGHT: 0.5; MFG_NAME01: Nexperia; MFG_PN01: 74AVC4T3144GU12X; ROHS: Yes; Supply Voltage: 0.8-3.6V; Temp Range: -40°C to 125°C; VOLTAGE: 0.8-3.6V
U68 = 74AUP1G07GW: IC LOGIC GATE BUFFER 0.8-3.6V TSSOP5; 3D_Mechanical_Footprint_File: http://fcl.am.freescale.net/ALLEGRO/step/sc70-5.STEP; AGILE_PN: 312-81232; CAD_APPROVED: Yes; HEIGHT: 1.1; MFG_NAME01: NEXPERIA; MFG_PN01: 74AUP1G07GW,125; ROHS: Yes; VOLTAGE: 0.8-3.6V
X1 = XTAL_13: XTAL 12Mhz 18pF -- SMD; AGILE_PN: 230-77934; CAD_APPROVED: Yes; EN: 108-1-00213; HEIGHT: 0.8; MFG_NAME01: TXC CORP; MFG_PN01: 7M-12.000MAAJ-T; ROHS: Yes

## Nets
GND: C1.2 C4.2 C8.2 C10.2 C11.2 C12.2 C13.2 C14.2 C20.2 C21.2 C31.2 C46.2 C128.2 C134.2 C135.2 C157.1 C161.2 C162.2 C171.2 C172.1 C177.2 C180.2 C184.2 C188.2 C189.2 C196.2 C197.2 C198.2 C199.2 C223.2 C225.2 C227.2 C228.2 C229.2 C230.2 C231.2 C233.2 C234.2 C235.2 C236.2 C258.2 C261.2 C263.2 C264.2 C266.2 C268.2 C273.2 C282.2 C287.2 C290.2 C292.2 C293.2 C297.2 C298.2 C299.2 C300.2 C302.2 C303.2 C305.2 C316.2 C318.2 GND2.1(TP) GND23.1(Pin1) GND24.1(Pin1) GND26.1(TP) GND27.1(TP) J7.3(A2) J7.5(A3) J10.2 J11.A1(GND1) J11.A12(GND2) J11.B1(GND4) J11.B12(GND3) J11.SH1 J11.SH2 J11.SH3 J11.SH4 Q1.2(SOURCE) Q3.2(SOURCE) Q4.2(SOURCE) Q5.2(SOURCE) Q6.2(SOURCE) R21.2 R26.2 R78.2 R284.2 R301.2 R302.2 R307.2 R308.2 R334.2 R337.2 R377.2 R378.2 R397.2 R399.2 R403.2 R411.2 R412.2 R417.2 R426.2 R432.2 TVS1.1(A1) TVS2.1(A1) TVS3.1(A1) U3.3(GND) U4.5(GND1) U4.6(GND2) U4.7(GND3) U4.8(GND4) U5.3(SEL) U5.5(GND1) U5.6(GND2) U5.7(GND3) U5.8(GND4) U7.2(GND) U13.9(VSS) U13.23(AD1) U13.24(AD2) U13.25(E_PAD) U14.3(GND) U28.1(GND1) U28.5(GND2) U28.10(AGND) U28.11(GND3) U28.13(TEST) U28.15(GND4) U28.25(GND5) U28.35(GND6) U28.47(GND7) U28.51(GND8) U40.4(LINEGND) U40.13(AGND) U50.2(GND) U53.3(GND) U54.B1(GND) U56.5(GND1) U56.6(GND2) U56.7(GND3) U56.8(GND4) U57.3(SEL) U57.5(GND1) U57.6(GND2) U57.7(GND3) U57.8(GND4) U60.10(GND1) U60.11(GND2) U61.4(GND) U62.4(GND) U63.10(GND1) U63.11(GND2) U65.6(GND) U66.3(GND) U68.3(GND) X1.2 X1.4 ; also on sheet 1 2 3 10 11 12 13 17 18 19 20 21 22 23 24
VBUS_DBG: J11.A4(VBUS1) J11.A9(VBUS2) J11.B4(VBUS4) J11.B9(VBUS3) L13.1 TVS3.2(A2)
VBUS_USB_DBG: C177.1 C184.1 C189.1 L13.2 U50.1(VIN) U50.3(EN)
VCC_FT_1V8: C261.1 C287.1 C290.1 L15.1 U28.12(VCORE1) U28.37(VCORE2) U28.64(VCORE3)
VCC_FT_3V3: C31.1 C46.1 C188.1 C223.1 C225.1 C229.1 C230.1 C231.1 C235.1 C236.1 C258.1 C263.1 C266.1 C273.1 C282.1 C299.1 C300.1 C318.1 D30.C L16.1 L17.1 R38.1 R60.1 R86.1 R103.1 R112.1 R172.1 R187.1 R198.1 R206.1 R219.2 R221.1 R226.2 R252.2 R255.2 R282.1 R413.1 R414.1 R415.1 TP160.1(TP) U13.21(VDD) U14.6(VCC) U28.20(VCCIO1) U28.31(VCCIO2) U28.42(VCCIO3) U28.50(VREGIN) U28.56(VCCIO4) U50.5(VOUT) U60.2(VCCB) U61.8(VCC) U62.8(VCC) U63.3(VCCA) U65.1(VCCA) U68.5(VCC) ; also on sheet 2
VDD_1V8: C297.1 C298.1 D20.A R257.1 R258.1 R300.1 U65.11(VCCB) ; also on sheet 2 10 11 19 22 23 24
VDD_3V3: C4.1 C20.1 C21.1 C161.1 C227.1 C228.1 C233.1 C234.1 C316.1 D30.A L18.2 R17.1 R306.1 R402.2 U3.5(VCC) U7.1(IN) U40.15(AVDD) U53.5(VCC) U60.3(VCCA) U63.2(VCCB) ; also on sheet 1 2 10 11 12 13 19 20 21 22 23 24
AUD_nMUTE: R308.1 U40.11(~{MUTE}) ; also on sheet 13
BT_MODE0: R431.2 U63.6(1A1)
BT_MODE1: R429.2 U63.7(1A2)
BT_MODE2: R428.2 U63.8(2A1)
BT_MODE3: R427.2 U63.9(2A2)
CON_JTAG_nRST: D22.C D23.C J7.10(B5) R259.2
DAC_BCLK: R278.2 U40.9(BCLK)
DAC_DAT: R297.2 U40.7(DACDAT)
DAC_LRCLK: R287.2 U40.8(LRCLK)
DAC_MCLK: R285.2 U40.10(MCLK)
DMIC_PDM_CLK: TP1.1(TP) U66.2(A) ; also on sheet 13
DMIC_PDM_DATA0: TP161.1(TP) U53.4(Y) ; also on sheet 13
DMIC_PDM_DATA1: TP2.1(TP) U3.4(Y) ; also on sheet 13
FSC_CTRL_H1: U61.7(1Y) ; also on sheet 2
FSC_CTRL_H2: U61.5(2Y) ; also on sheet 2
FT_BMODE_DIR: R432.1 U13.14(IO1_4) U63.4(1DIR) U63.5(2DIR)
FT_BOOT_MODE0: R431.1 U13.1(IO0_0)
FT_BOOT_MODE1: R429.1 U13.2(IO0_1)
FT_BOOT_MODE2: R428.1 U13.3(IO0_2)
FT_BOOT_MODE3: R427.1 U13.4(IO0_3)
FT_CTRL_H1: R413.2 U13.5(IO0_4) U61.1(1A)
FT_CTRL_H2: R414.2 U13.6(IO0_5) U61.3(2A)
FT_CTRL_H3: TP18.1(Pin1) U13.7(IO0_6)
FT_EECLK: U28.62(EECLK) ; also on sheet 2
FT_EECS: U28.63(EECS) ; also on sheet 2
FT_EEDATA: U28.61(EEDATA) ; also on sheet 2
FT_EXP_SCL: R45.2 U13.19(SCL)
FT_EXP_SDA: R51.2 U13.20(SDA)
FT_IO_nINT1: R64.1 U28.30(BDBUS4)
FT_nPWREN: TP136.1(Pin1) U28.60(~{PWREN})
FT_nSUSPEND: TP99.1(Pin1) U28.36(~{SUSPEND})
FT_ONOFF: R397.1 U13.12(IO1_2) U62.3(2A)
FT_OSCI: C128.1 U28.2(OSCI) X1.1
FT_OSCO: C134.1 U28.3(OSCO) X1.3
FT_POR_B: R417.1 U13.10(IO1_0) U62.6(3A)
FT_RC_SEL: R77.1 U13.13(IO1_3)
FT_SCL: R45.1 R255.1 U28.26(BDBUS0) ; also on sheet 2
FT_SD_CD: U13.16(IO1_6) U68.2(A)
FT_SD_CD_EN: U68.4(Y) ; also on sheet 24
FT_SD_PWR_EN: U61.2(3Y) ; also on sheet 24
FT_SD_PWREN: R415.2 U13.15(IO1_5) U61.6(3A)
FT_SDA: R51.1 R252.1 U28.27(BDBUS1) U28.28(BDBUS2) ; also on sheet 2
FT_SYS_nRST: R399.1 U13.11(IO1_1) U62.1(1A)
FT_TST0: R178.1 U28.21(ADBUS4)
FT_TST1: R194.1 U28.22(ADBUS5)
FT_TST2: R212.1 U28.23(ADBUS6)
FT_TST3: R225.1 U28.24(ADBUS7)
FT_USB_DN: U28.7(USBDM) U54.C1(CH1_OUT+)
FT_USB_DP: U28.8(USBDP) U54.C2(CH1_OUT-)
FTA_TCK: U28.16(ADBUS0) U65.2(A1)
FTA_TDI: U28.17(ADBUS1) U65.3(A2)
FTA_TDO: U28.18(ADBUS2) U65.5(YA4)
FTA_TMS: U28.19(ADBUS3) U65.4(A3)
FTC_RXD: D16.C(CATHODE) R409.1 U28.39(CDBUS1)
FTC_TXD: D17.C(CATHODE) R410.1 U28.38(CDBUS0)
HP_J_L: C171.1 J10.4 R335.2 TP162.1(TP) TVS2.2(A2)
HP_J_R: C172.2 J10.3 R336.2 TP163.1(TP) TVS1.2(A2)
JTG_TCK: J7.4(B2) U65.10(YB1) ; also on sheet 13
JTG_TDI: J7.8(B4) R258.2 U65.9(YB2) ; also on sheet 13
JTG_TDO: J7.6(B3) U65.7(B4) ; also on sheet 13
JTG_TMS: J7.2(B1) R257.2 U65.8(YB3) ; also on sheet 13
LINE_L: C166.1 R335.1 U40.1(LINEVOUTL)
LINE_R: C165.1 R336.1 U40.16(LINEVOUTR)
LINEVDD: C305.1 L18.1 U40.6(LINEVDD)
ONOFF: R416.2 ; also on sheet 3 23
PDM_CLK_1V8: R3.1 R4.1 R371.1 R372.1 U66.4(Y)
PDM_D0: R379.2 R384.2 U53.2(A)
PDM_D1: R12.2 R13.2 U3.2(A)
PMIC_ON_REQ: Q5.1(GATE) ; also on sheet 3 12 19
PMIC_STBY_REQ: Q6.1(GATE) ; also on sheet 3 19
POR_B: D23.A Q4.1(GATE) R398.2 ; also on sheet 3 19
RC_BT_MODE0: U63.15(1B1) ; also on sheet 1
RC_BT_MODE1: U63.14(1B2) ; also on sheet 1
RC_BT_MODE2: U63.13(2B1) ; also on sheet 1
RC_BT_MODE3: U63.12(2B2) ; also on sheet 1
RC_nSEL: D5.C(CATHODE) Q1.3(DRAIN) R103.2 U63.1(~{1OE}) U63.16(~{2OE}) U65.12(~{OE})
RC_SEL: Q1.1(GATE) R425.2 R426.1 U14.4(Y)
REG_FT_1V8: C264.1 C268.1 L15.2 TP115.1(TP) U28.49(VREGOUT)
SAI1_DAC_MCLK: R285.1 TP148.1(Pin1) ; also on sheet 13
SAI1_DAC_TXC: R278.1 TP146.1(Pin1) ; also on sheet 13
SAI1_DAC_TXD: R297.1 TP150.1(Pin1) ; also on sheet 13
SAI1_DAC_TXFS: R287.1 TP149.1(Pin1) ; also on sheet 13
SYS_nRST: D22.A R418.2 ; also on sheet 19 23
UART1_RXD: R401.2 TP186.1(TP) ; also on sheet 20
UART1_TXD: R400.2 TP187.1(TP) ; also on sheet 1 20
USB_DBG_CC1: J11.A5(CC1) R377.1
USB_DBG_CC2: J11.B5(CC2) R378.1
USB_DBG_DN: J11.A7(DN1) J11.B7(DN2) U54.A1(CH1_IN+)
USB_DBG_DP: J11.A6(DP1) J11.B6(DP2) U54.A2(CH1_IN-)
VMIC_1V8: C1.1 C8.1 C10.1 C11.1 C12.1 C13.1 C14.1 C22.1 C196.1 C197.1 C198.1 C199.1 R18.1 TP6.1(TP) U4.3(SEL) U4.4(VDD) U5.4(VDD) U7.5(OUT) U56.3(SEL) U56.4(VDD) U57.4(VDD) U66.5(VCC)
VTREF: J7.1(A1) R300.2
WDOG_B: Q3.1(GATE) ; also on sheet 19 20
N117397706: C162.1 U40.2(CPVOUTN)
N117397841: C157.2 U40.14(VMID)
N117397843: C149.1 U40.5(CPCA)
N117397886: C149.2 U40.3(CPCB)
N117397940: R306.2 R307.1 U40.12(AIFMODE)
N117398055: C165.2 R334.1
N117398057: C166.2 R337.1
N117466193: R379.1 U56.1(DAT)
N117466207: R12.1 U4.1(DAT)
N117466246: R371.2 U56.2(CLK)
N117466262: R4.2 U4.2(CLK)
N117466578: R384.1 U57.1(DAT)
N117466582: R13.1 U5.1(DAT)
N117466611: R372.2 U57.2(CLK)
N117466616: R3.2 U5.2(CLK)
N117466869: C22.2 R18.2 R26.1 U7.4(NC)
N117466881: R17.2 U7.3(EN)
N117474140: C292.1 C302.1 L16.2 U28.9(VPLL)
N117474237: C180.1 U50.4(BP)
N117474317: R403.1 U60.4(1DIR)
N117474345: R402.1 U60.5(2DIR)
N117474374: R412.1 U60.1(~{1OE})
N117474402: R411.1 U60.16(~{2OE})
N117474428: C293.1 C303.1 L17.2 U28.4(VPHY)
N117474503: R410.2 U60.15(1B1)
N117474505: R401.1 U60.6(1A1)
N117474615: R409.2 U60.13(2B1)
N117474617: R400.1 U60.8(2A1)
N117475319: TP122.1(Pin1) U28.29(BDBUS3)
N117475358: TP114.1(Pin1) U28.32(BDBUS5)
N117475382: TP101.1(Pin1) U28.33(BDBUS6)
N117475402: TP100.1(Pin1) U28.34(BDBUS7)
N117475466: D17.A(ANODE) R219.1
N117475515: D16.A(ANODE) R226.1
N117475774: TP97.1(Pin1) U28.48(DDBUS0)
N117475802: TP123.1(Pin1) U28.52(DDBUS1)
N117475809: C135.1 R282.2 U28.14(~{RESET})
N117475826: R284.1 U28.6(REF)
N117476127: R418.1 U62.7(1Y)
N117476217: R416.1 U62.5(2Y)
N117476285: R60.2 R64.2 U13.22(~{INT})
N117476287: R21.1 R38.2 U13.18(AD0)
N117476313: R398.1 U62.2(3Y)
N117476531: D5.A(ANODE) R112.2
N117476554: TP15.1(Pin1) U13.8(IO0_7)
N117476682: R86.2 U14.1(OE)
N117476684: TP13.1(Pin1) U13.17(IO1_7)
N117476744: R77.2 R78.1 R425.1 U14.2(A)
N117477451: Q3.3(DRAIN) R172.2 R178.2
N117477453: Q4.3(DRAIN) R187.2 R194.2
N117477455: Q5.3(DRAIN) R198.2 R212.2
N117477457: D15.A(ANODE) R206.2
N117477459: D15.C(CATHODE) Q6.3(DRAIN) R221.2 R225.2
N117477506: D20.C R259.1
N117477781: J7.7(A4) R301.1
N117477804: J7.9(A5) R302.1

Not connected (* = marked no-connect by the designer): J10 1* 5* 6*; J11 A2(SSTXP1)* A3(SSTXN1)* A8(SBU1)* A10(SSRXN2)* A11(SSRXP2)* B2(SSTXP2)* B3(SSTXN2)* B8(SBU2)* B10(SSRXN1)* B11(SSRXP1)*; U3 1(NC)*; U14 5(NC)*; U28 40(CDBUS2)* 41(CDBUS3)* 43(CDBUS4)* 44(CDBUS5)* 45(CDBUS6)* 46(CDBUS7)* 53(DDBUS2)* 54(DDBUS3)* 55(DDBUS4)* 57(DDBUS5)* 58(DDBUS6)* 59(DDBUS7)*; U53 1(NC)*; U60 7(1A2)* 9(2A2)* 12(2B2)* 14(1B2)*; U66 1(NC)*; U68 1(NC)*

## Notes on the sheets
sheet 7
- i.MX SoC RC I/F
- REMOTE DEBUG
- REMOVE THIS PAGE IF NOT USED!!!
- UART BUF
- LDO
- BUFF
- -33PB
- FT PWR
- DIR:
  H:   An -> Bn
  L:   Bn -> An
- # UART1: CORTEX-A CONSOLE
- BOOT MODE RC
- DIR:
- Direction CTRL used for BT_MODE Read/Write
- H:   An -> Bn
  L:   Bn -> An
- OVER DRV BT MODE
  READ BACK BT MODE
- FT-JTAG / IO
- MPSSE MODE
- TCK/SK
  TDI/DO
  TDO/DI
  TMS/CS
  GPIOL0
  GPIOL1
  GPIOL2
  GPIOL3
- # FT_TST0-3 used for system automation test
- DIP SW
- BOOT_MODE[3:0]: PU/PD
- BOOT_MODE[3:0]
- CPU
- Z:90 OHM
- MPSSE MODE
- SDA_TX
- TCK/SK
  TDI/DO
  TDO/DI
  TMS/CS
  GPIOL0
  GPIOL1
  GPIOL2
  GPIOL3
- FT-I2C / IO
- SDA_RX
- BUFF
- OE=H:  nAn/nBn high-impedance (Z)
- DIR:
  H:   An -> Bn
  L:   Bn -> An
- o
- OE=L: EN
- ASYNC Serial MODE
- i
- RS232/Bit-Bang
  RS233/Bit-Bang
  RS234/Bit-Bang
  RS235/Bit-Bang
  RS236/Bit-Bang
  RS237/Bit-Bang
  RS238/Bit-Bang
  RS239/Bit-Bang
- FT-DBG A
- # UART1: CORTEX-A CONSOLE
- Prevent 'H/L' confilct
- FT-IO EXP
- ASYNC Serial MODE
- RS232/Bit-Bang
  RS233/Bit-Bang
  RS234/Bit-Bang
  RS235/Bit-Bang
  RS236/Bit-Bang
  RS237/Bit-Bang
  RS238/Bit-Bang
  RS239/Bit-Bang
- FT-DBG M
- BOOT_MODE[3:0]: RC_GPIO
- ONOFF / RST RC
- PWREN# = 0: Normal operation.
  PWREN# =1 : USB SUSPEND mode or device has not been configured.
- SUSPEND#: Active low when USB is in suspend mode.
- IO EXP
- # Triple inverter w/ OD outputs
- CPU
- OD
- BTN
- OD
- FT-GPIO
- # 'H' active
- OD
- I/O
- I/O
- I/O
- I/O
- 1 MHz I2C (Fm+)
- O
- O
- O
- O
- A=L:  Y= high-impedance (Z)
- O
- A=H:  Y= L
- O
- O
- O
- JTAG DBG
- O
- O
- O
- OE=H, EN
- OE=L, DIS Default
- FT-JTAG
- #I2C ADDR: 0b'0100001x
- Power-on default state is input with 100K pull-up
- VTREF
- CPU
- JTAG CN
- OE=H:  YBn/YA4 high-impedance (Z)
- OE=L:  EN
- CTL Signal Isolation
- JTAG HDR
- SYS TST/ MONITOR
- # Triple w/ OD outputs
- TMS
- TCK
- OD
- TDO
- TDI
- nRST
- OD
- FT-GPIO
- # Warm RST, CPU ONLY
- OD
- A=H:  Y= high-impedance (Z)
- A=L:  Y= L
- CPU
- Default High to enable power load switch, use buffer to avoid leakage.
- Note:
- # SYS Cold RST
- If USB debug cable is not plugged in, the control signals can still be high as default.
- #VGSth: 0.6-0.9-1.1V
- STATUS LED
- OD
- LED
- COLOR
- ON
- OFF
- A=H:  Y= high-impedance (Z)
- A=L:  Y= L
- D28
- D5
- GREEN
- RED
- Remote DBG
- SYS PWR ON
- Local DBG
- SYS OFF
- D15
- ORANGE
- SYS SUSPEND
- RUN
- D16
- GREEN
- DBG TX Low
- DBG TX High
- D17
- ORANGE
- DBG RX Low
- DBG RX High
- Note:
- Default High to enable SD card detect, use buffer to avoid leakage.
- If USB debug cable is not plugged in, the control signals can still be high as default.
sheet 8
- PDM MIC
- LDO 1.8V for DMIC
- CLK Buffer
- VIN: 1.2V-5.5V
- LDO
- R1
- Vfb=0.8V
- R2
- DIS CHG: 280 0HM
- Vout=(1+R1/R2)*Vfb
- # FB = 0.8V
- # 1.80V: R1/R2 = 1.0/0.8 : 15K/12K
- Sec SRC:
  150mA:   LDCL015MR (ADJ)
  300mA:   RT9078N-08GJ5
  350mA:   UM1750S-18
  450mA:   NCP161ASN180T1G
- 300mA:   RT9078N-08GJ5
  350mA:   UM1750S-18
  450mA:   NCP161ASN180T1G
sheet 9
- AUDIO DAC
- 24-bit 192kHz Stereo DAC 2Vrms Line Out
- HP JACK
- 3.5mm POLE
- HSL
- HSR
- GND
- MIC
- CTIA Standard
